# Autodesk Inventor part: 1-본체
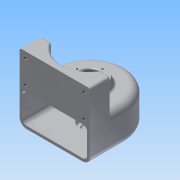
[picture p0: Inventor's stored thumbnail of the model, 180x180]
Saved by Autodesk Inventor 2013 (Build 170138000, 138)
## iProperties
Created: 2015-02
Part Number: 1-본체
Material: 알루미늄 6061
Document SubType Name: Modeling
Designer: Administrator
Density: 2.40731 g/cm^3
Mass: 511.244 g
Surface Area: 706.56 cm^2
Volume: 212.371 cm^3
Author: Administrator
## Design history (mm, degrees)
sketch "스케치1"
  geometry: L1 (-50, -50)-(50, -50); L2 (50, -50)-(50, 0); L3 (-50, 0)-(-50, -50); A1 r 50 centre (0, 0) between (50, 0) and (-50, 0); 1 further point
  constraints: 6 end point, 2 point on circle, 2 tangent, 1 centre point, 1 coincident, 1 horizontal, 1 parallel, 1 perpendicular
  dimensions: "d0" = 50 distance from line of L1 point (0, 0); "d1" = 50 radius of A1
extrude "돌출1" new body sketch "스케치1" distance "d2" = 50; taper "d3" = 0 deg
fillet "모깎기1" dims "d4" = 10
feature "쉘1" dims "d5" = 4
node "작업 평면1"
sketch "스케치2"
  geometry: C1 r 20 at (0, 0); 1 further point
  constraints: 1 centre point, 1 coincident
  dimensions: "d7" = 40 diameter of C1
extrude "돌출2" join sketch "스케치2" stored distance "d9" = 50; taper "d10" = 0 deg
hole "구멍1" diameter "d13" = 20; stored, may be unused: countersink angle "d17" = 90 deg, drill point angle "d19" = 0 deg; dims "d11" = 10, "d12" = 10, "d14" = 6, "d15" = 28, "d16" = 8, "d18" = 10
sketch "스케치4"
  geometry: C1 r 25 at (0, 0); A1 r 40 centre (0, 0) between (40, 0) and (-40, 0) reference
  constraints: 1 centre point, 1 coincident
  dimensions: "d21" = 50 diameter of C1
extrude "돌출3" join sketch "스케치4" distance "d23" = 10; taper "d24" = -20 deg
hole "구멍2" diameter "d27" = 20; stored, may be unused: countersink angle "d31" = 90 deg, drill point angle "d33" = 0 deg; dims "d25" = 10, "d26" = 10, "d28" = 6, "d29" = 28, "d30" = 10, "d32" = 10
node "작업 평면4"
sketch "스케치7"
  geometry: L1 (50, -20)-(34.641, -20); L2 (-50, -20)-(-34.641, -20); L3 (-40, -50)-(-50, -50) reference; L4 (-50, -20)-(-50, -50); L5 (50, -50)-(50, -20); L6 (-50, -50)-(50, -50); A1 r 40 centre (0, 0) between (-34.641, -20) and (34.641, -20); 1 further point
  constraints: 10 end point, 2 collinear, 2 equal length, 2 point on circle, 1 centre point, 1 coincident, 1 horizontal, 1 perpendicular
  dimensions: "d39" = 40 radius of A1; "d41" = 30 distance between parallel lines of L3 L2; "d42" = 100 distance of L1.start L2.start
extrude "돌출4" join sketch "스케치7" stored distance "d43" = 10; taper "d44" = 0 deg
sketch "스케치8"
  geometry: L1 (-10, 95)-(90, 95) reference; L2 (81.75, 53)-(-1.75, 53); L3 (-1.75, 53)-(-1.75, 86); L4 (-1.75, 86)-(81.75, 86); L5 (81.75, 86)-(81.75, 53); 7 further points
  constraints: 8 end point, 4 coincident, 2 midpoint, 2 parallel, 1 horizontal, 1 perpendicular, 1 vertical alignment
  dimensions: "d45" = 83.5 distance of L3.end L4.end; "d47" = 9 distance between parallel lines of L4 L1; "d48" = 33 distance of L2.end L3.end
hole "구멍3" sketch "스케치8" at (-1.75, 86), (-1.75, 53), (81.75, 53), (81.75, 86) diameter "d49" = 5.134; stored, may be unused: countersink angle "d53" = 90 deg, drill point angle "d55" = 118 deg; dims "d50" = 10, "d51" = 28, "d52" = 10, "d54" = 13
sketch "스케치9"
  geometry: C1 r 14 at (0, 0) reference; 1 further point
  constraints: 1 vertical alignment
  dimensions: "d56" = 18 distance of point (0, 18) C1.centre
hole "구멍4" sketch "스케치9" at (0, 18) diameter "d57" = 2.459; stored, may be unused: countersink angle "d61" = 90 deg, drill point angle "d63" = 118 deg; dims "d58" = 6, "d59" = 28, "d60" = 10, "d62" = 9
fillet "모깎기2" dims "d67" = 0.3, "d68" = 3
fillet "모깎기3" dims "d69" = 3
chamfer "모따기1" distance "d70" = 1; stored, may be unused: second distance "d71" = 2, angle "d72" = 45 deg
node "작업 평면5"
sketch "스케치10"
  geometry: L1 (17, -9)-(-17, -9) reference; L2 (40, 0)-(-40, 0) reference; 2 further points
  constraints: 1 vertical alignment, 1 other
  dimensions: "d76" = 25 distance from line of point (0, 25) L2
feature "엠보싱1" sketch "스케치10" dims "d15" = 28, "d74" = 0.5, "d75" = 0
node "솔리드1"
pattern_circular "원형 패턴1" dims angle "d65" = 360 deg
other parameters: "d6" = 9, "d38" = -95
